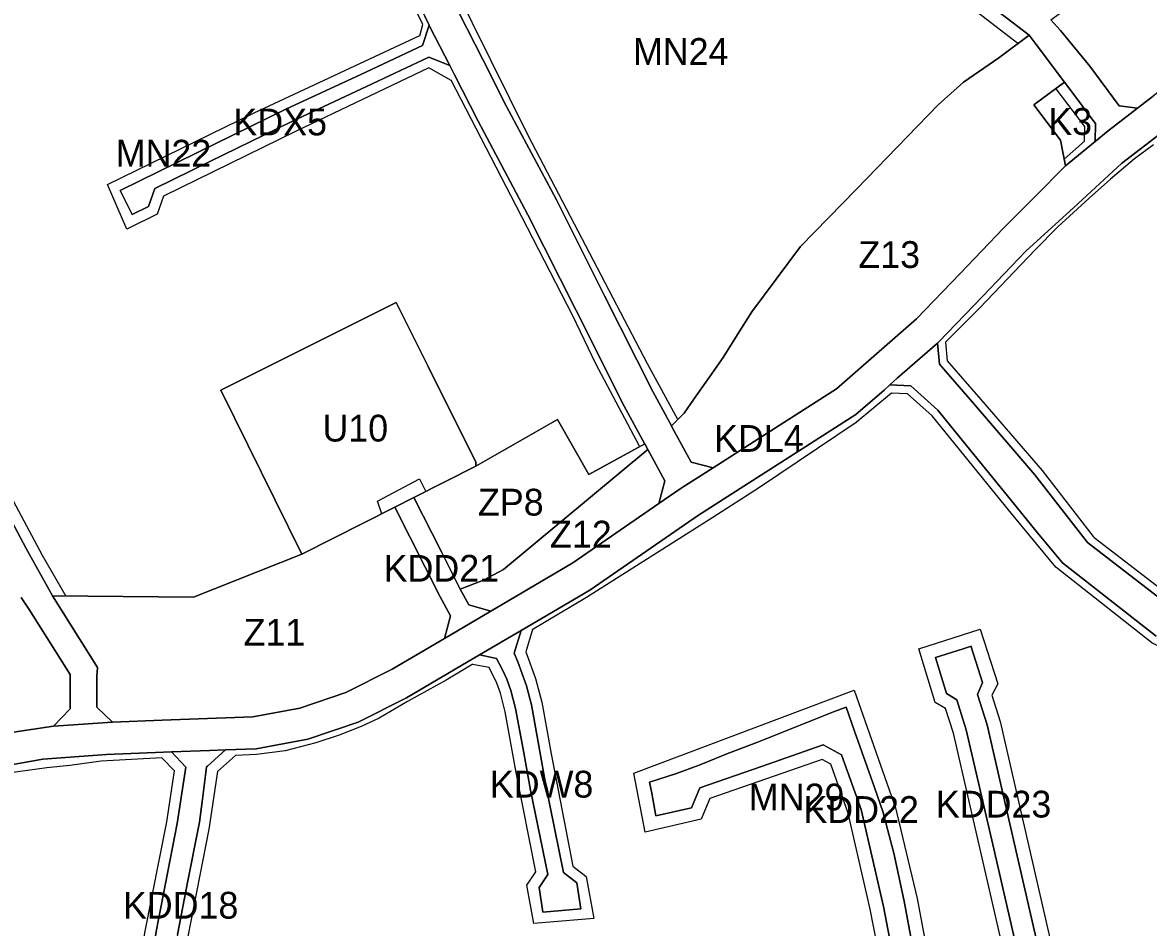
# Model space of a CAD drawing. Extents: x 7428841 to 7433518, y 5545054 to 5546840.
# Drawn here: x 7430661.7 to 7431082.1, y 5545462.1 to 5545800.1 of the extents above; entities that cross this region are included whole.
import ezdxf

# ---------------------------------------------------------------- set-up
doc = ezdxf.new("R2010")
doc.units = 0
for name, color, linetype in [('linie_rozgraniczajace', 7, 'Continuous'), ('linie_zabudowy_nieprzekraczalne', 7, 'Continuous'), ('oznaczenia_przeznaczen', 7, 'Continuous')]:
    doc.layers.add(name, color=color, linetype=linetype)

msp = doc.modelspace()

# ---------------------------------------------------------------- linework, layer by layer
at = {"layer": 'linie_rozgraniczajace'}
for points in [[(7431045.61, 5545801.14), (7431067.88, 5545817.29), (7431076.57, 5545821.79), (7431084.03, 5545826.97), (7431103.49, 5545832.51), (7431124.51, 5545838.5), (7431134.63, 5545844.49), (7431140.43, 5545848.13), (7431144.77, 5545850.84), (7431152.52, 5545821.69), (7431149.64, 5545813.17), (7431132.13, 5545804.74), (7431116.5, 5545795.25), (7431100.86, 5545785.75), (7431083.98, 5545772.74), (7431078.01, 5545768.14), (7431071.09, 5545769), (7431060.22, 5545783.81), (7431049.22, 5545797.1)], [(7430698.11, 5545737.34), (7430726.79, 5545751.43), (7430759.99, 5545767.75), (7430787.95, 5545780.77), (7430810.99, 5545791.51), (7430813.52, 5545799.14), (7430813.82, 5545798.52), (7430821.19, 5545784.06), (7430813.45, 5545787.14), (7430790.17, 5545776.26), (7430762.21, 5545763.2), (7430731.68, 5545748.27), (7430711.05, 5545738.12), (7430708.77, 5545731.43), (7430702.6, 5545728.4)], [(7430903.98, 5545649.49), (7430908.75, 5545654.22), (7430912.38, 5545659.43), (7430918.32, 5545667.94), (7430923.28, 5545675.05), (7430928.65, 5545683.57), (7430934.02, 5545692.08), (7430952.2, 5545716.53), (7430973.06, 5545737.84), (7431003.52, 5545769.42), (7431013.07, 5545777.85), (7431026.2, 5545786.9), (7431037.59, 5545795.36), (7431040.21, 5545791.88), (7431050.7, 5545777.91), (7431039.32, 5545769.35), (7431049.2, 5545756.14), (7431051.16, 5545746.55), (7431039.56, 5545734.95), (7431027.95, 5545723.35), (7431011.72, 5545706.43), (7430995.48, 5545689.51), (7430965.59, 5545663.32), (7430936.61, 5545644.78), (7430919.52, 5545633.85), (7430911.33, 5545635.96), (7430904.16, 5545649.16)], [(7431039.32, 5545769.35), (7431050.7, 5545777.91), (7431055.66, 5545771.31), (7431060.61, 5545764.72), (7431062.27, 5545762.47), (7431062.23, 5545755.71), (7431051.16, 5545746.55), (7431049.2, 5545756.14)], [(7430735.69, 5545662.88), (7430801.15, 5545695.53), (7430813.06, 5545671.9), (7430830.89, 5545635.91), (7430830.99, 5545634.48), (7430807.83, 5545622.73), (7430800.65, 5545619.09), (7430765.97, 5545601.51)], [(7430807.83, 5545622.73), (7430830.99, 5545634.48), (7430861.47, 5545651.88), (7430873.15, 5545631.32), (7430893.98, 5545642.76), (7430895.14, 5545640.63), (7430841.26, 5545595.82), (7430833.76, 5545591.9), (7430825.13, 5545588.53), (7430818.11, 5545602.48)], [(7430825.13, 5545588.53), (7430833.76, 5545591.9), (7430841.26, 5545595.82), (7430895.14, 5545640.63), (7430895.14, 5545640.63), (7430901.47, 5545628.97), (7430899.3, 5545620.49), (7430867.12, 5545598.27), (7430836.55, 5545580.31), (7430828.3, 5545582.68)], [(7430800.65, 5545619.09), (7430807.83, 5545622.73), (7430818.11, 5545602.48), (7430825.13, 5545588.53), (7430828.3, 5545582.68), (7430836.55, 5545580.31), (7430819.19, 5545570.11), (7430821.48, 5545578.48), (7430817.61, 5545585.61)], [(7430672.86, 5545585.97), (7430725.57, 5545585.55), (7430765.97, 5545601.51), (7430800.65, 5545619.09), (7430817.61, 5545585.61), (7430821.48, 5545578.48), (7430819.19, 5545570.11), (7430799.65, 5545558.62), (7430782.37, 5545549.96), (7430765.18, 5545544.07), (7430747.66, 5545540.84), (7430730.77, 5545540.22), (7430713.89, 5545539.6), (7430695.35, 5545538.85), (7430689.44, 5545544.38), (7430689.48, 5545555.99), (7430689.75, 5545559.16), (7430689.67, 5545559.29)], [(7430832.37, 5545563.95), (7430847.86, 5545573.04), (7430845.23, 5545564.6), (7430846.63, 5545561.35), (7430849.81, 5545552.43), (7430851.67, 5545545.26), (7430854.46, 5545529.93), (7430857.25, 5545514.6), (7430863.66, 5545482.68), (7430868.61, 5545478.8), (7430870.1, 5545469.11), (7430855.91, 5545467.89), (7430854.57, 5545477.06), (7430857.84, 5545481.86), (7430851.36, 5545513.47), (7430848.58, 5545528.71), (7430845.81, 5545543.96), (7430844.06, 5545550.67), (7430842.55, 5545554.91), (7430840.72, 5545558.6), (7430838.66, 5545562.6)], [(7431002.55, 5545562.92), (7431012.92, 5545566.24), (7431015.88, 5545567.2), (7431015.94, 5545567), (7431020.07, 5545553.65), (7431018.27, 5545549.15), (7431021.86, 5545537.79), (7431031.71, 5545494.92), (7431041.57, 5545452.05), (7431048.4, 5545446.86), (7431038.71, 5545445.48), (7431029.31, 5545443.81), (7431033.75, 5545450.33), (7431023.91, 5545493.16), (7431014.06, 5545536), (7431010.49, 5545547.22), (7431006.69, 5545549.52)], [(7430698.5, 5545411.3), (7430705.41, 5545417.58), (7430711.59, 5545460.59), (7430719.46, 5545500.94), (7430722.64, 5545522.01), (7430717.28, 5545527.72), (7430731.66, 5545528.25), (7430737.53, 5545528.46), (7430730.79, 5545522.39), (7430730.41, 5545522.08), (7430730.14, 5545519.97), (7430728.86, 5545510.07), (7430727.76, 5545501.48), (7430727.34, 5545499.58), (7430723.43, 5545479.52), (7430719.51, 5545459.45), (7430713.91, 5545420.49), (7430719.79, 5545415.07)]]:
    msp.add_lwpolyline(points, close=True, dxfattribs=at)
for points in [[(7430793.31, 5545841.15), (7430813.52, 5545799.14), (7430810.99, 5545791.51), (7430787.95, 5545780.77), (7430759.99, 5545767.75), (7430726.79, 5545751.43), (7430698.11, 5545737.34), (7430702.6, 5545728.4), (7430708.77, 5545731.43), (7430711.05, 5545738.12), (7430731.68, 5545748.27), (7430762.21, 5545763.2), (7430790.17, 5545776.26), (7430813.45, 5545787.14), (7430821.19, 5545784.06), (7430822.81, 5545780.87), (7430831.8, 5545763.23), (7430850.35, 5545728.35), (7430868.35, 5545692.57), (7430886.35, 5545656.8), (7430893.91, 5545642.89), (7430893.98, 5545642.76), (7430873.15, 5545631.32), (7430861.47, 5545651.88), (7430830.99, 5545634.48), (7430830.89, 5545635.91), (7430813.06, 5545671.9), (7430801.15, 5545695.53), (7430735.69, 5545662.88), (7430765.97, 5545601.51), (7430725.57, 5545585.55), (7430672.86, 5545585.97), (7430663.1, 5545603.69), (7430635.16, 5545655.99)], [(7430824.57, 5545803.85), (7430833.51, 5545786.31), (7430842.45, 5545768.77), (7430851.73, 5545751.31), (7430861.01, 5545733.86), (7430879, 5545698.11), (7430896.99, 5545662.36), (7430903.98, 5545649.49), (7430904.16, 5545649.16), (7430911.33, 5545635.96), (7430919.52, 5545633.85), (7430907.63, 5545626.24), (7430899.3, 5545620.49), (7430901.47, 5545628.97), (7430895.14, 5545640.63), (7430895.14, 5545640.63), (7430893.98, 5545642.76), (7430893.91, 5545642.89), (7430886.35, 5545656.8), (7430868.35, 5545692.57), (7430850.35, 5545728.35), (7430831.8, 5545763.23), (7430822.81, 5545780.87), (7430821.19, 5545784.06), (7430813.82, 5545798.52), (7430813.52, 5545799.14), (7430793.31, 5545841.15)], [(7431018.04, 5545810.46), (7431037.59, 5545795.36), (7431026.2, 5545786.9), (7431013.07, 5545777.85), (7431003.52, 5545769.42), (7430973.06, 5545737.84), (7430952.2, 5545716.53), (7430934.02, 5545692.08), (7430928.65, 5545683.57), (7430923.28, 5545675.05), (7430918.32, 5545667.94), (7430912.38, 5545659.43), (7430908.75, 5545654.22), (7430903.98, 5545649.49), (7430896.99, 5545662.36), (7430879, 5545698.11), (7430861.01, 5545733.86), (7430851.73, 5545751.31), (7430842.45, 5545768.77), (7430833.51, 5545786.31), (7430824.57, 5545803.85)], [(7431045.61, 5545801.14), (7431049.22, 5545797.1), (7431060.22, 5545783.81), (7431071.09, 5545769), (7431078.01, 5545768.14), (7431067.09, 5545759.73), (7431062.23, 5545755.71), (7431062.27, 5545762.47), (7431060.61, 5545764.72), (7431055.66, 5545771.31), (7431050.7, 5545777.91), (7431040.21, 5545791.88), (7431037.59, 5545795.36), (7431018.04, 5545810.46)], [(7430653.27, 5545534.31), (7430673.27, 5545537.3), (7430684.31, 5545538.07), (7430695.35, 5545538.85), (7430713.89, 5545539.6), (7430730.77, 5545540.22), (7430747.66, 5545540.84), (7430765.18, 5545544.07), (7430782.37, 5545549.96), (7430799.65, 5545558.62), (7430819.19, 5545570.11), (7430836.55, 5545580.31), (7430867.12, 5545598.27), (7430899.3, 5545620.49), (7430907.63, 5545626.24), (7430919.52, 5545633.85), (7430936.61, 5545644.78), (7430965.59, 5545663.32), (7430995.48, 5545689.51), (7431011.72, 5545706.43), (7431027.95, 5545723.35), (7431039.56, 5545734.95), (7431051.16, 5545746.55), (7431062.23, 5545755.71), (7431067.09, 5545759.73), (7431078.01, 5545768.14), (7431083.98, 5545772.74)], [(7431087.62, 5545759.46), (7431072.01, 5545747.44), (7431054.18, 5545731.1), (7431036.34, 5545714.77), (7431020.06, 5545697.8), (7431003.78, 5545680.83), (7431003.29, 5545680.4), (7430988.3, 5545667.27), (7430985.52, 5545664.78), (7430983.39, 5545662.87), (7430972.81, 5545653.7), (7430943.46, 5545634.92), (7430914.1, 5545616.14), (7430873.5, 5545588.1), (7430847.86, 5545573.04), (7430832.37, 5545563.95), (7430805.03, 5545547.9), (7430787.02, 5545538.87), (7430768.23, 5545532.43), (7430748.98, 5545528.88), (7430737.53, 5545528.46), (7430731.66, 5545528.25), (7430717.28, 5545527.72), (7430714.35, 5545527.61), (7430693.05, 5545526.75), (7430669.3, 5545524.96), (7430655.35, 5545522.49)], [(7431003.29, 5545680.4), (7431003.78, 5545680.83), (7431020.06, 5545697.8), (7431036.34, 5545714.77), (7431054.18, 5545731.1), (7431072.01, 5545747.44), (7431087.62, 5545759.46)], [(7431084.96, 5545570.99), (7431050, 5545598.37), (7431040.63, 5545609.48), (7431032.64, 5545619.34), (7431008.17, 5545649.46), (7431003.47, 5545655.29), (7430993.34, 5545664.46), (7430985.52, 5545664.78), (7430988.3, 5545667.27), (7431003.29, 5545680.4), (7431004.04, 5545672.58), (7431017.15, 5545657.43), (7431039.65, 5545631.21), (7431059.28, 5545605.97), (7431091.4, 5545581.18)], [(7431091.4, 5545581.18), (7431059.28, 5545605.97), (7431039.65, 5545631.21), (7431017.15, 5545657.43), (7431004.04, 5545672.58), (7431003.29, 5545680.4)], [(7430719.51, 5545459.45), (7430723.43, 5545479.52), (7430727.34, 5545499.58), (7430727.76, 5545501.48), (7430728.86, 5545510.07), (7430730.14, 5545519.97), (7430730.41, 5545522.08), (7430730.79, 5545522.39), (7430737.53, 5545528.46), (7430748.98, 5545528.88), (7430768.23, 5545532.43), (7430787.02, 5545538.87), (7430805.03, 5545547.9), (7430832.37, 5545563.95), (7430838.66, 5545562.6), (7430840.72, 5545558.6), (7430842.55, 5545554.91), (7430844.06, 5545550.67), (7430845.81, 5545543.96), (7430848.58, 5545528.71), (7430851.36, 5545513.47), (7430857.84, 5545481.86), (7430854.57, 5545477.06), (7430855.91, 5545467.89), (7430870.1, 5545469.11), (7430868.61, 5545478.8), (7430863.66, 5545482.68), (7430857.25, 5545514.6), (7430854.46, 5545529.93), (7430851.67, 5545545.26), (7430849.81, 5545552.43), (7430846.63, 5545561.35), (7430845.23, 5545564.6), (7430847.86, 5545573.04), (7430873.5, 5545588.1), (7430914.1, 5545616.14), (7430943.46, 5545634.92), (7430972.81, 5545653.7), (7430983.39, 5545662.87), (7430985.52, 5545664.78), (7430993.34, 5545664.46), (7431003.47, 5545655.29), (7431008.17, 5545649.46), (7431032.64, 5545619.34), (7431040.63, 5545609.48), (7431050, 5545598.37), (7431084.96, 5545570.99)], [(7430635.16, 5545655.99), (7430663.1, 5545603.69), (7430672.86, 5545585.97), (7430689.67, 5545559.29), (7430689.75, 5545559.16), (7430689.48, 5545555.99), (7430689.44, 5545544.38), (7430695.35, 5545538.85), (7430684.31, 5545538.07), (7430673.27, 5545537.3), (7430679.44, 5545543.81), (7430679.5, 5545556.67), (7430664.22, 5545580.93), (7430661.23, 5545585.41)], [(7430661.23, 5545585.41), (7430664.22, 5545580.93), (7430679.5, 5545556.67), (7430679.44, 5545543.81), (7430673.27, 5545537.3), (7430653.27, 5545534.31)], [(7431041.57, 5545452.05), (7431031.71, 5545494.92), (7431021.86, 5545537.79), (7431018.27, 5545549.15), (7431020.07, 5545553.65), (7431015.94, 5545567), (7431015.88, 5545567.2), (7431012.92, 5545566.24), (7431002.55, 5545562.92), (7431006.69, 5545549.52), (7431010.49, 5545547.22), (7431014.06, 5545536), (7431023.91, 5545493.16), (7431033.75, 5545450.33)], [(7430996.06, 5545443.73), (7430990.86, 5545472), (7430986.96, 5545489.93), (7430982.89, 5545505.41), (7430979.73, 5545514.43), (7430972.32, 5545535.49), (7430969.18, 5545544.38), (7430964.46, 5545542.72), (7430935.91, 5545531.28), (7430924.7, 5545527.01), (7430916.15, 5545523.51), (7430913.91, 5545522.62), (7430905.82, 5545519.66), (7430895.77, 5545516.37), (7430896.65, 5545512.24), (7430898.18, 5545503.81), (7430911.43, 5545506.83), (7430914.57, 5545514.33), (7430937.62, 5545522.31), (7430960.66, 5545530.3), (7430967.52, 5545526.56), (7430974.76, 5545506.18), (7430983.11, 5545470.03), (7430988.24, 5545443.3)], [(7430988.24, 5545443.3), (7430983.11, 5545470.03), (7430974.76, 5545506.18), (7430967.52, 5545526.56), (7430960.66, 5545530.3), (7430937.62, 5545522.31), (7430914.57, 5545514.33), (7430911.43, 5545506.83), (7430898.18, 5545503.81), (7430896.65, 5545512.24), (7430895.77, 5545516.37), (7430905.82, 5545519.66), (7430913.91, 5545522.62), (7430916.15, 5545523.51), (7430924.7, 5545527.01), (7430935.91, 5545531.28), (7430964.46, 5545542.72), (7430969.18, 5545544.38), (7430972.32, 5545535.49), (7430979.73, 5545514.43), (7430982.89, 5545505.41), (7430986.96, 5545489.93), (7430990.86, 5545472), (7430996.06, 5545443.73)], [(7430655.35, 5545522.49), (7430669.3, 5545524.96), (7430693.05, 5545526.75), (7430714.35, 5545527.61), (7430717.28, 5545527.72), (7430722.64, 5545522.01), (7430719.46, 5545500.94), (7430711.59, 5545460.59), (7430705.41, 5545417.58), (7430698.5, 5545411.3), (7430667.19, 5545405.74), (7430649.43, 5545392.37)]]:
    msp.add_lwpolyline(points, dxfattribs=at)
at = {"layer": 'linie_zabudowy_nieprzekraczalne'}
for points in [[(7430788.18, 5545883.83), (7430850.37, 5545758.09), (7430894.92, 5545672.75), (7430906.23, 5545651.94)], [(7431033.36, 5545792.32), (7430994.66, 5545822.18), (7430980.92, 5545845.44), (7430967.38, 5545868.84)], [(7430810.05, 5545795.21), (7430811.15, 5545799.44), (7430811.15, 5545799.44), (7430786.06, 5545850.56)], [(7430558.4, 5545807.72), (7430590.08, 5545747.77), (7430614.37, 5545702.84), (7430650.25, 5545636.23), (7430669.09, 5545601.23), (7430677.86, 5545585.93)], [(7430821.79, 5545778.53), (7430813.43, 5545783.15), (7430763.83, 5545759.61), (7430714.3, 5545735.26), (7430712.02, 5545728.58), (7430700.6, 5545722.96), (7430693.38, 5545739.63), (7430748.2, 5545766.41), (7430810.07, 5545795.31)], [(7430892.11, 5545641.96), (7430875.75, 5545672.66), (7430867.11, 5545690.63), (7430846.04, 5545731.73), (7430821.69, 5545778.56)], [(7431058.23, 5545755.78), (7431058.33, 5545761.35), (7431047.58, 5545775.43)], [(7431050.56, 5545749.16), (7431058.23, 5545755.78)], [(7431083.98, 5545754.5), (7431083.98, 5545754.5), (7431076.84, 5545749.27), (7431067.95, 5545741.69), (7431059.9, 5545734.59), (7431048.2, 5545723.83), (7431039.8, 5545715.27), (7431019.1, 5545693.51), (7431006.28, 5545680.69)], [(7431006.28, 5545680.69), (7431006.93, 5545673.82), (7431019.43, 5545659.38), (7431042.41, 5545632.81), (7431061.42, 5545608.11), (7431061.75, 5545607.85)], [(7430986.15, 5545661.67), (7430972.98, 5545650.69), (7430936.47, 5545626.19), (7430919.4, 5545615.24), (7430872.25, 5545585.44), (7430852.02, 5545573.36)], [(7431047.49, 5545596.7), (7431030.31, 5545617.45), (7431001.28, 5545653.22), (7430992.13, 5545661.51), (7430986.15, 5545661.67)], [(7430795.88, 5545616.67), (7430794.19, 5545621.4), (7430809.9, 5545629.75), (7430812.29, 5545625)], [(7431061.75, 5545607.85), (7431093, 5545583.73), (7431137.29, 5545562.66)], [(7431209.77, 5545497.53), (7431205.22, 5545501.45), (7431178.09, 5545520.83), (7431130.72, 5545544.64), (7431083.34, 5545568.44), (7431047.49, 5545596.7)], [(7430852.14, 5545573.41), (7430849.64, 5545565.04), (7430853.26, 5545555.15), (7430855.6, 5545546.27), (7430859.06, 5545527.02), (7430867.11, 5545485), (7430872.19, 5545481.2), (7430874.95, 5545465.53), (7430852.64, 5545463.59), (7430850.01, 5545477.93), (7430853.36, 5545482.86), (7430845.96, 5545519.96), (7430841.94, 5545542.68), (7430840.16, 5545549.61), (7430838.76, 5545553.4), (7430835.93, 5545559.2), (7430829.72, 5545560.38)], [(7431025.61, 5545447.22), (7431028.39, 5545451.34), (7431009.24, 5545534.68), (7431006.3, 5545543.91), (7431002.48, 5545546.22), (7430996.31, 5545566.17), (7431019.27, 5545573.53), (7431025.83, 5545553.18), (7431023.58, 5545548.95), (7431026.69, 5545539.1), (7431046.03, 5545454.93), (7431050.82, 5545451.3)], [(7430829.8, 5545560.42), (7430819.85, 5545554.48), (7430805.41, 5545546.5), (7430794.91, 5545540.31), (7430788.12, 5545537.2), (7430779.94, 5545533.98), (7430771.24, 5545531.09), (7430759.74, 5545528.09), (7430749.03, 5545526.69), (7430741.21, 5545526.39)], [(7430979.9, 5545439.11), (7430982.97, 5545444.23), (7430978.21, 5545469), (7430969.95, 5545504.78), (7430963.45, 5545523.09), (7430960.21, 5545524.85), (7430918.32, 5545510.33), (7430915.04, 5545502.53), (7430894.19, 5545497.77), (7430889.94, 5545519.73), (7430972.23, 5545550.76), (7430987.68, 5545506.87), (7430995.76, 5545472.98), (7431000.67, 5545446.32), (7431003.99, 5545443.38)], [(7430713.74, 5545525.55), (7430702.41, 5545524.91), (7430691.04, 5545524.2), (7430679.33, 5545522.67), (7430670.81, 5545521.77), (7430659.92, 5545520.25), (7430642.73, 5545517.62), (7430632.81, 5545516.12), (7430612.76, 5545513), (7430607.77, 5545512.58), (7430585.31, 5545510.76), (7430577.66, 5545510.42), (7430571.68, 5545510.52), (7430559.65, 5545511.42)], [(7430696.65, 5545415.04), (7430701.65, 5545419.57), (7430707.41, 5545460.11), (7430715.52, 5545501.63), (7430718.39, 5545520.69), (7430713.74, 5545525.55)], [(7430741.21, 5545526.39), (7430734.53, 5545520.37), (7430731.28, 5545498.9), (7430723.45, 5545458.79), (7430718.16, 5545422.01), (7430720.92, 5545419.33)]]:
    msp.add_lwpolyline(points, dxfattribs=at)

# ---------------------------------------------------------------- texts
at = {"layer": 'oznaczenia_przeznaczen'}
for s, p in [('MN24', (7430889.61, 5545784.32)), ('KDX5', (7430740.43, 5545757.99)), ('K3', (7431044.66, 5545758.17)), ('MN22', (7430696.5, 5545746.33)), ('Z13', (7430973.77, 5545708.47)), ('U10', (7430773.67, 5545643.64)), ('KDL4', (7430919.89, 5545639.78)), ('ZP8', (7430831.75, 5545615.98)), ('Z12', (7430858.64, 5545604.04)), ('KDD21', (7430796.53, 5545591.29)), ('Z11', (7430744.23, 5545567.41)), ('KDW8', (7430836.18, 5545510.65)), ('MN29', (7430932.89, 5545505.85)), ('KDD22', (7430953.26, 5545501.18)), ('KDD23', (7431002.69, 5545503.2)), ('KDD18', (7430699.19, 5545465.44))]:
    msp.add_text(s, height=10, dxfattribs=at).set_placement(p)

doc.saveas('drawing.dxf')
